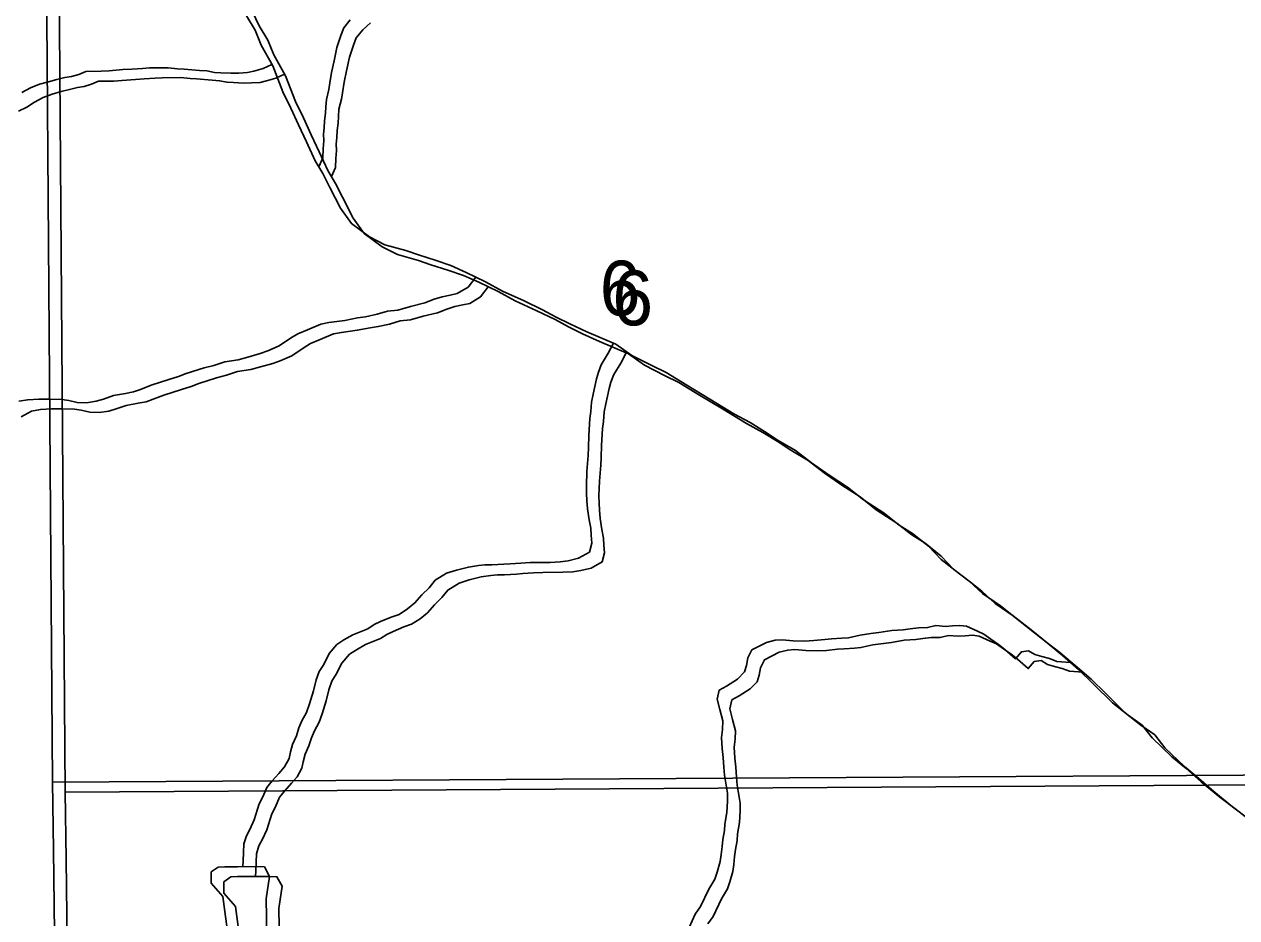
# Model space of a CAD drawing. Extents: x -21.1 to 50.3, y -4.9 to 22.1.
# Drawn here: x 44.072 to 44.997, y 18.617 to 19.298 of the extents above; entities that cross this region are included whole.
import ezdxf

# ---------------------------------------------------------------- set-up
doc = ezdxf.new("R2010")
doc.units = 0
for name, color, linetype in [('GM_X_Major_River', 7, 'Continuous'), ('GM_X_Minor_Lake', 7, 'Continuous'), ('GM_X_Minor_River', 7, 'Continuous'), ('GM_X_Section', 7, 'Continuous'), ('GM_X_Section_Text', 7, 'Continuous')]:
    doc.layers.add(name, color=color, linetype=linetype)

msp = doc.modelspace()

# ---------------------------------------------------------------- linework, layer by layer
at = {"layer": 'GM_X_Major_River'}
for points in [[(44.24162, 19.30473), (44.24815, 19.29377), (44.25278, 19.28242), (44.26162, 19.26654), (44.26934, 19.24685), (44.27549, 19.23437), (44.28128, 19.22151), (44.28744, 19.20865), (44.29398, 19.19427), (44.29974, 19.18444), (44.30513, 19.17385), (44.3132, 19.15797), (44.32163, 19.14626), (44.33535, 19.13611), (44.34716, 19.13012), (44.36312, 19.12569), (44.37262, 19.12234), (44.38555, 19.11826), (44.39733, 19.11417), (44.40913, 19.10894), (44.42397, 19.10184), (44.43691, 19.09472), (44.45327, 19.08725), (44.46735, 19.08052), (44.47763, 19.0749), (44.48829, 19.06966), (44.50123, 19.06369), (44.52329, 19.05436), (44.53549, 19.04572), (44.55071, 19.03786), (44.56175, 19.03262), (44.57737, 19.02287), (44.59489, 19.01237), (44.61317, 19.00112), (44.62573, 18.99437), (44.63678, 18.98762), (44.64707, 18.98086), (44.6604, 18.97299), (44.6726, 18.96359), (44.68594, 18.9542), (44.70004, 18.94519), (44.71224, 18.93541), (44.72787, 18.92527), (44.73931, 18.91625), (44.74959, 18.90987), (44.7618, 18.90009), (44.77135, 18.88991), (44.78317, 18.88089), (44.7927, 18.87337), (44.80301, 18.86395), (44.81673, 18.85456), (44.83046, 18.84365), (44.84267, 18.83387), (44.8522, 18.82635), (44.86403, 18.81657), (44.87624, 18.80603), (44.88731, 18.7951), (44.90217, 18.78045)], [(44.24625, 19.30782), (44.25126, 19.29723), (44.25779, 19.28627), (44.26242, 19.27492), (44.27125, 19.25904), (44.27898, 19.23935), (44.28513, 19.22687), (44.29091, 19.21401), (44.29707, 19.20114), (44.30362, 19.18677), (44.30938, 19.17694), (44.31476, 19.16635), (44.32284, 19.15047), (44.33127, 19.13876), (44.34499, 19.12861), (44.35679, 19.12262), (44.37275, 19.11819), (44.38226, 19.11484), (44.39518, 19.11076), (44.40697, 19.10667), (44.41876, 19.10144), (44.4336, 19.09434), (44.44655, 19.08722), (44.46291, 19.07975), (44.47699, 19.07302), (44.48727, 19.0674), (44.49793, 19.06216), (44.51086, 19.05619), (44.53293, 19.04686), (44.54512, 19.03822), (44.56035, 19.03036), (44.57139, 19.02512), (44.587, 19.01537), (44.60453, 19.00487), (44.62281, 18.99361), (44.63537, 18.98687), (44.64642, 18.98012), (44.65671, 18.97336), (44.67003, 18.96549), (44.68224, 18.95609), (44.69558, 18.9467), (44.70968, 18.93769), (44.72188, 18.92791), (44.7375, 18.91777), (44.74894, 18.90875), (44.75923, 18.90237), (44.77143, 18.89259), (44.78099, 18.88241), (44.79281, 18.87339), (44.80234, 18.86586), (44.81265, 18.85645), (44.82637, 18.84706), (44.8401, 18.83615), (44.8523, 18.82637), (44.86184, 18.81885), (44.87367, 18.80907), (44.88588, 18.79853), (44.89695, 18.7876), (44.91181, 18.77295)], [(44.90217, 18.78045), (44.91401, 18.77106), (44.92469, 18.76355), (44.93236, 18.75375), (44.94728, 18.73945), (44.95835, 18.73043), (44.96981, 18.72028), (44.98395, 18.70863), (44.9954, 18.69999), (45.00648, 18.69135)], [(44.91181, 18.77295), (44.92364, 18.76356), (44.93433, 18.75605), (44.942, 18.74625), (44.95691, 18.73195), (44.96799, 18.72293), (44.97945, 18.71278), (44.99359, 18.70113), (45.00504, 18.69249)]]:
    msp.add_lwpolyline(points, dxfattribs=at)
at = {"layer": 'GM_X_Minor_Lake'}
for points in [[(44.21461, 18.65156), (44.21467, 18.64283), (44.22347, 18.63265), (44.22789, 18.60043), (44.2322, 18.58186), (44.23497, 18.56556), (44.24714, 18.56224), (44.26028, 18.57943), (44.25707, 18.60294), (44.25649, 18.63102), (44.25901, 18.64812), (44.25517, 18.6553), (44.24947, 18.65564)], [(44.24947, 18.65564), (44.23471, 18.65552), (44.2251, 18.65552), (44.22001, 18.65515), (44.21461, 18.65156)], [(44.22425, 18.64406), (44.22431, 18.63533), (44.23311, 18.62515), (44.23752, 18.59293), (44.24183, 18.57436), (44.24461, 18.55806), (44.25677, 18.55474), (44.26992, 18.57193), (44.26671, 18.59544), (44.26612, 18.62352), (44.26865, 18.64062), (44.2648, 18.6478), (44.25911, 18.64814)], [(44.25911, 18.64814), (44.24435, 18.64802), (44.23474, 18.64802), (44.22965, 18.64764), (44.22425, 18.64406)]]:
    msp.add_lwpolyline(points, dxfattribs=at)
at = {"layer": 'GM_X_Minor_River'}
for points in [[(44.29672, 19.18961), (44.2998, 19.19656), (44.30012, 19.20341), (44.30045, 19.20949), (44.3004, 19.21444), (44.30074, 19.21938), (44.30108, 19.22471), (44.30179, 19.23042), (44.30213, 19.23536), (44.30246, 19.24107), (44.3043, 19.24869), (44.30502, 19.25364), (44.30647, 19.26163), (44.3083, 19.2704), (44.31049, 19.28068), (44.31345, 19.28983), (44.31569, 19.29555), (44.32058, 19.30167)], [(44.30635, 19.18211), (44.30943, 19.18906), (44.30975, 19.19591), (44.31008, 19.20199), (44.31004, 19.20693), (44.31038, 19.21188), (44.31071, 19.21721), (44.31143, 19.22292), (44.31176, 19.22786), (44.3121, 19.23357), (44.31393, 19.24119), (44.31465, 19.24614), (44.3161, 19.25413), (44.31793, 19.26289), (44.32013, 19.27318), (44.32309, 19.28233), (44.32532, 19.28805), (44.33021, 19.29417), (44.33625, 19.29955)], [(44.26099, 19.26767), (44.25435, 19.26463), (44.24714, 19.26267), (44.24221, 19.26149), (44.23575, 19.26106), (44.22967, 19.26101), (44.22206, 19.26133), (44.21711, 19.26167), (44.2114, 19.26276), (44.20569, 19.2631), (44.1939, 19.26414), (44.18895, 19.26448), (44.18172, 19.26518), (44.16765, 19.26507), (44.16233, 19.26465), (44.15397, 19.2642), (44.14713, 19.26376), (44.13687, 19.26292), (44.13079, 19.26249), (44.11901, 19.26239), (44.1137, 19.26007), (44.10801, 19.2585), (44.10308, 19.2577), (44.097, 19.25613), (44.09056, 19.25455), (44.08373, 19.2526), (44.0769, 19.24988), (44.07009, 19.2464)], [(44.27062, 19.26017), (44.26399, 19.25713), (44.25678, 19.25517), (44.25185, 19.25399), (44.24539, 19.25356), (44.2393, 19.25351), (44.2317, 19.25383), (44.22675, 19.25417), (44.22103, 19.25526), (44.21533, 19.2556), (44.20353, 19.25664), (44.19859, 19.25698), (44.19136, 19.25768), (44.17729, 19.25757), (44.17197, 19.25714), (44.16361, 19.2567), (44.15677, 19.25626), (44.14651, 19.25542), (44.14043, 19.25499), (44.12864, 19.25489), (44.12334, 19.25257), (44.11765, 19.251), (44.11271, 19.2502), (44.10664, 19.24863), (44.10019, 19.24705), (44.09336, 19.2451), (44.08654, 19.24238), (44.07973, 19.2389), (44.07406, 19.23505), (44.06762, 19.23196)], [(44.41636, 19.10548), (44.41052, 19.09784), (44.4022, 19.09283), (44.39688, 19.09164), (44.39081, 19.09045), (44.38474, 19.0885), (44.37754, 19.08578), (44.36654, 19.08303), (44.35706, 19.08029), (44.34908, 19.07947), (44.34111, 19.07712), (44.33238, 19.07515), (44.32631, 19.07434), (44.31644, 19.07236), (44.30428, 19.07073), (44.29821, 19.06955), (44.28798, 19.06528), (44.28078, 19.06218), (44.27511, 19.05871), (44.26641, 19.05294), (44.2577, 19.04906), (44.25201, 19.04712), (44.24253, 19.04438), (44.23532, 19.04242), (44.22507, 19.04081), (44.21673, 19.03808), (44.20914, 19.03612), (44.19549, 19.03183), (44.1898, 19.0295), (44.18222, 19.02716), (44.16895, 19.02287), (44.1606, 19.01976), (44.1553, 19.01781), (44.14922, 19.01662), (44.14011, 19.01502), (44.13253, 19.0123), (44.12684, 19.01073), (44.11963, 19.00953), (44.1124, 19.00986), (44.10592, 19.01132), (44.10059, 19.01204), (44.09147, 19.01235), (44.0831, 19.01228), (44.07474, 19.01183), (44.06791, 19.01063)], [(44.426, 19.09798), (44.42016, 19.09033), (44.41183, 19.08532), (44.40652, 19.08414), (44.40045, 19.08295), (44.39438, 19.081), (44.38718, 19.07828), (44.37618, 19.07553), (44.36669, 19.07279), (44.35871, 19.07196), (44.35075, 19.06962), (44.34202, 19.06765), (44.33594, 19.06684), (44.32607, 19.06486), (44.31392, 19.06323), (44.30785, 19.06204), (44.29762, 19.05778), (44.29042, 19.05468), (44.28474, 19.05121), (44.27605, 19.04544), (44.26734, 19.04156), (44.26165, 19.03961), (44.25217, 19.03688), (44.24496, 19.03492), (44.2347, 19.03331), (44.22636, 19.03058), (44.21877, 19.02862), (44.20512, 19.02432), (44.19944, 19.022), (44.19185, 19.01965), (44.17858, 19.01536), (44.17024, 19.01225), (44.16493, 19.01031), (44.15886, 19.00912), (44.14975, 19.00752), (44.14217, 19.0048), (44.13648, 19.00323), (44.12926, 19.00203), (44.12204, 19.00236), (44.11556, 19.00382), (44.11023, 19.00454), (44.1011, 19.00485), (44.09274, 19.00478), (44.08438, 19.00433), (44.07754, 19.00313), (44.06959, 18.99889)], [(44.52148, 19.05512), (44.51741, 19.04737), (44.51216, 19.03859), (44.50993, 19.03286), (44.50845, 19.02791), (44.50589, 19.0161), (44.5048, 19.01001), (44.5041, 19.00278), (44.50339, 18.99745), (44.50274, 18.98451), (44.50243, 18.97539), (44.5021, 18.9693), (44.50107, 18.95712), (44.50078, 18.94609), (44.50083, 18.94039), (44.50125, 18.93507), (44.50169, 18.92861), (44.5029, 18.92025), (44.5041, 18.9138), (44.50452, 18.90848), (44.50495, 18.9024), (44.50311, 18.89554), (44.49478, 18.89091), (44.48681, 18.88894), (44.48074, 18.88813), (44.47314, 18.88769), (44.45793, 18.88757), (44.45071, 18.88713), (44.44273, 18.88668), (44.43779, 18.88626), (44.42867, 18.88581), (44.42334, 18.88577), (44.4184, 18.88534), (44.41081, 18.88414), (44.4017, 18.88179), (44.39412, 18.87944), (44.38542, 18.87405), (44.38091, 18.86831), (44.37525, 18.86294), (44.36998, 18.85681), (44.36431, 18.8522), (44.35788, 18.84797), (44.35182, 18.84602), (44.34386, 18.84253), (44.33894, 18.84021), (44.33402, 18.83713), (44.32265, 18.83247), (44.31584, 18.82861), (44.31055, 18.82515), (44.30452, 18.81825), (44.30041, 18.80985), (44.29703, 18.8045), (44.29481, 18.79802), (44.2926, 18.78964), (44.28964, 18.77973), (44.28741, 18.77325), (44.28367, 18.76675), (44.28143, 18.76141), (44.27958, 18.75531), (44.27659, 18.74882), (44.27512, 18.74311), (44.27402, 18.73815), (44.27065, 18.73166), (44.26613, 18.72668), (44.26124, 18.72094), (44.2571, 18.71596), (44.25412, 18.70871), (44.25112, 18.70337), (44.24742, 18.69117), (44.24406, 18.68391), (44.24144, 18.67895), (44.23959, 18.67285), (44.23927, 18.66638), (44.23894, 18.65992), (44.23886, 18.65555)], [(44.53111, 19.04762), (44.52705, 19.03987), (44.5218, 19.03108), (44.51957, 19.02536), (44.51809, 19.02041), (44.51553, 19.0086), (44.51444, 19.00251), (44.51374, 18.99528), (44.51302, 18.98995), (44.51237, 18.97701), (44.51207, 18.96789), (44.51174, 18.9618), (44.5107, 18.94962), (44.51042, 18.93859), (44.51046, 18.93289), (44.51089, 18.92757), (44.51133, 18.92111), (44.51254, 18.91275), (44.51373, 18.9063), (44.51416, 18.90098), (44.51459, 18.8949), (44.51275, 18.88804), (44.50442, 18.88341), (44.49645, 18.88144), (44.49038, 18.88063), (44.48278, 18.88019), (44.46757, 18.88007), (44.46035, 18.87963), (44.45236, 18.87918), (44.44743, 18.87876), (44.4383, 18.87831), (44.43298, 18.87826), (44.42804, 18.87784), (44.42045, 18.87664), (44.41134, 18.87429), (44.40375, 18.87194), (44.39506, 18.86655), (44.39054, 18.86081), (44.38489, 18.85544), (44.37961, 18.84931), (44.37395, 18.8447), (44.36752, 18.84047), (44.36145, 18.83852), (44.3535, 18.83503), (44.34857, 18.83271), (44.34366, 18.82963), (44.33229, 18.82497), (44.32548, 18.82111), (44.32018, 18.81765), (44.31416, 18.81075), (44.31005, 18.80235), (44.30667, 18.797), (44.30444, 18.79052), (44.30223, 18.78214), (44.29928, 18.77223), (44.29705, 18.76575), (44.2933, 18.75925), (44.29107, 18.75391), (44.28922, 18.74781), (44.28623, 18.74132), (44.28476, 18.73561), (44.28366, 18.73065), (44.28029, 18.72416), (44.27577, 18.71918), (44.27088, 18.71344), (44.26674, 18.70846), (44.26375, 18.70121), (44.26076, 18.69586), (44.25706, 18.68367), (44.2537, 18.67641), (44.25108, 18.67145), (44.24923, 18.66535), (44.2489, 18.65888), (44.24858, 18.65242), (44.24849, 18.64805)], [(44.87008, 18.81134), (44.85972, 18.81212), (44.85399, 18.81436), (44.84828, 18.81583), (44.84294, 18.81731), (44.83797, 18.82031), (44.83266, 18.81951), (44.82814, 18.81415), (44.82009, 18.82131), (44.81512, 18.82507), (44.80938, 18.8292), (44.80403, 18.83297), (44.79906, 18.83521), (44.79067, 18.83894), (44.78572, 18.83966), (44.78002, 18.83923), (44.7747, 18.83881), (44.76747, 18.83951), (44.76102, 18.83794), (44.75417, 18.83788), (44.74771, 18.83707), (44.7424, 18.83627), (44.73366, 18.83581), (44.72378, 18.83421), (44.71771, 18.8334), (44.70973, 18.8322), (44.70063, 18.83022), (44.69568, 18.8298), (44.6877, 18.82936), (44.68276, 18.82894), (44.67441, 18.82811), (44.66719, 18.82767), (44.65844, 18.82798), (44.65007, 18.82867), (44.64475, 18.82825), (44.6383, 18.82667), (44.62694, 18.82088), (44.62395, 18.81477), (44.62285, 18.80906), (44.62138, 18.8041), (44.6161, 18.79873), (44.60778, 18.79334), (44.6021, 18.79026), (44.60064, 18.7834), (44.60261, 18.77543), (44.60496, 18.7667), (44.60464, 18.76024), (44.60393, 18.75415), (44.60438, 18.74579), (44.6052, 18.73895), (44.60564, 18.73135), (44.60608, 18.72527), (44.60847, 18.7116), (44.60852, 18.70551), (44.60784, 18.69676), (44.60639, 18.688), (44.60605, 18.68306), (44.60497, 18.6762), (44.60425, 18.67087), (44.60355, 18.66479), (44.60283, 18.65946), (44.60062, 18.65145), (44.59876, 18.64611), (44.59426, 18.63847), (44.58791, 18.62511), (44.58378, 18.61937), (44.5793, 18.60907)], [(44.87972, 18.80384), (44.86935, 18.80462), (44.86363, 18.80686), (44.85791, 18.80833), (44.85258, 18.80981), (44.84761, 18.81281), (44.84229, 18.81201), (44.83778, 18.80665), (44.82973, 18.81381), (44.82475, 18.81757), (44.81902, 18.8217), (44.81366, 18.82546), (44.8087, 18.82771), (44.8003, 18.83144), (44.79535, 18.83216), (44.78965, 18.83173), (44.78433, 18.83131), (44.7771, 18.83201), (44.77065, 18.83044), (44.76381, 18.83038), (44.75735, 18.82957), (44.75203, 18.82876), (44.74329, 18.82831), (44.73342, 18.82671), (44.72735, 18.8259), (44.71937, 18.8247), (44.71026, 18.82272), (44.70532, 18.8223), (44.69734, 18.82186), (44.6924, 18.82143), (44.68404, 18.82061), (44.67682, 18.82017), (44.66807, 18.82048), (44.6597, 18.82117), (44.65438, 18.82075), (44.64793, 18.81917), (44.63658, 18.81338), (44.63358, 18.80727), (44.63249, 18.80156), (44.63101, 18.7966), (44.62574, 18.79123), (44.61742, 18.78584), (44.61174, 18.78275), (44.61028, 18.7759), (44.61225, 18.76793), (44.6146, 18.7592), (44.61427, 18.75274), (44.61357, 18.74664), (44.61402, 18.73829), (44.61483, 18.73145), (44.61528, 18.72385), (44.61571, 18.71776), (44.61811, 18.7041), (44.61816, 18.69801), (44.61747, 18.68926), (44.61603, 18.6805), (44.61569, 18.67556), (44.61461, 18.6687), (44.61389, 18.66337), (44.61318, 18.65729), (44.61247, 18.65196), (44.61025, 18.64395), (44.6084, 18.63861), (44.6039, 18.63097), (44.59755, 18.61761), (44.59341, 18.61187)]]:
    msp.add_lwpolyline(points, dxfattribs=at)
at = {"layer": 'GM_X_Section'}
for points in [[(44.08631, 19.71488), (45.12856, 19.71587), (45.13143, 18.72623), (44.0935, 18.71999)], [(44.09595, 19.70738), (45.1382, 19.70837), (45.14107, 18.71873), (44.10314, 18.71249)], [(44.0935, 18.71999), (45.13143, 18.72623), (45.14863, 17.70187), (44.10665, 17.68876), (44.1055, 17.74068), (44.09428, 18.66845)], [(44.10314, 18.71249), (45.14107, 18.71873), (45.15827, 17.69437), (44.11629, 17.68126), (44.11514, 17.73318), (44.10391, 18.66095)]]:
    msp.add_lwpolyline(points, close=True, dxfattribs=at)

# ---------------------------------------------------------------- texts
at = {"layer": 'GM_X_Section_Text'}
for p in [(44.51092, 19.0761), (44.52056, 19.0686)]:
    msp.add_text('6', height=0.04186, rotation=0.00001, dxfattribs=at).set_placement(p)

doc.saveas('drawing.dxf')
